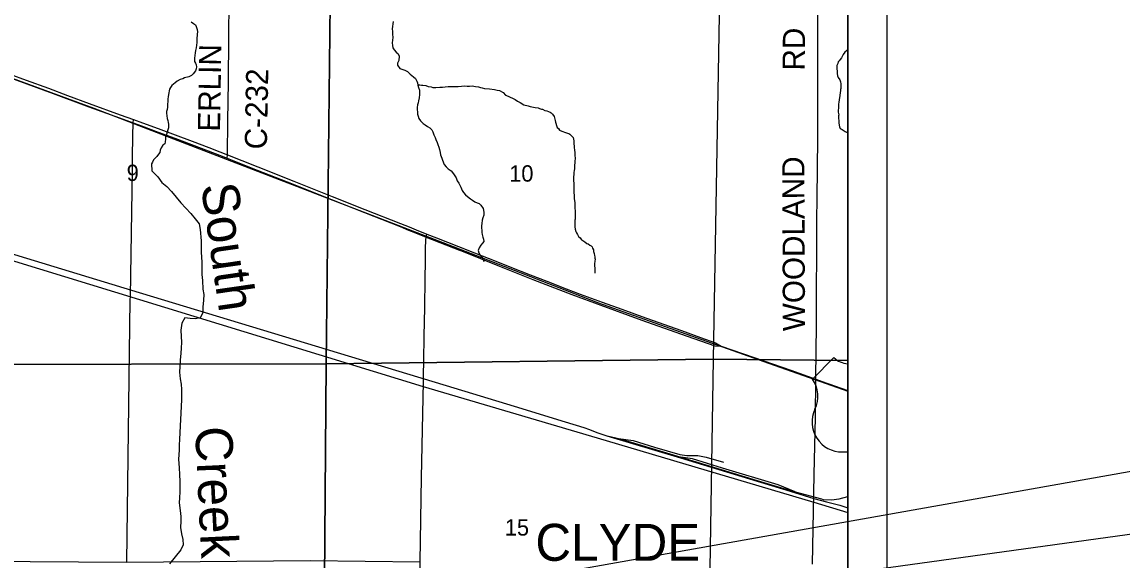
# Model space of a CAD drawing. Extents: x 36.7 to 70.7, y 0 to 22.
# Drawn here: x 43.478 to 46.296, y 17.404 to 18.785 of the extents above; entities that cross this region are included whole.
import ezdxf

# ---------------------------------------------------------------- set-up
doc = ezdxf.new("R2010")
doc.units = 0
for name, color, linetype in [('Default', 7, 'Continuous'), ('GM_X_Corporation_Text', 7, 'Continuous'), ('GM_X_County_Road', 7, 'Continuous'), ('GM_X_County_Road_Text', 7, 'Continuous'), ('GM_X_Minor_River', 7, 'Continuous'), ('GM_X_Minor_River_Text', 7, 'Continuous'), ('GM_X_Rail_Line', 7, 'Continuous'), ('GM_X_Section', 7, 'Continuous'), ('GM_X_Section_Text', 7, 'Continuous'), ('GM_X_State_Shield', 7, 'Continuous'), ('GM_X_Township_Road', 7, 'Continuous'), ('GM_X_Township_Road_Text', 7, 'Continuous'), ('GM_X_US_Route', 7, 'Continuous'), ('SH_Data', 7, 'Continuous'), ('SH_Text', 7, 'Continuous')]:
    doc.layers.add(name, color=color, linetype=linetype)

msp = doc.modelspace()

# ---------------------------------------------------------------- linework, layer by layer
at = {"layer": 'Default'}
for points in [[(45.5934, 17.918), (45.5934, 18.9006), (45.2652, 18.9013), (45.2484, 17.9213)], [(45.5934, 16.8994), (45.5934, 17.918), (45.2484, 17.9213), (45.2325, 16.9015)]]:
    msp.add_lwpolyline(points, close=True, dxfattribs=at)
at = {"layer": 'GM_X_County_Road'}
msp.add_line((45.503, 17.3961), (45.5047, 17.4867), dxfattribs=at)
for points in [[(44.0037, 18.4362), (44.004, 18.445), (44.0053, 18.5319), (44.0064, 18.6321), (44.0077, 18.7436), (44.0085, 18.8412), (44.0087, 18.9088), (44.0173, 19.4198)], [(45.5047, 17.4867), (45.5055, 17.532), (45.5076, 17.6263), (45.5108, 17.7725), (45.5115, 17.8705)], [(43.2502, 17.4045), (43.7467, 17.4014), (44.216, 17.4059), (44.498, 17.4024)]]:
    msp.add_lwpolyline(points, dxfattribs=at)
at = {"layer": 'GM_X_Minor_River'}
for points in [[(43.9114, 18.7853), (43.9174, 18.7815), (43.9219, 18.7773), (43.9241, 18.7731), (43.9267, 18.7654), (43.927, 18.7597), (43.9266, 18.7537), (43.926, 18.7408), (43.926, 18.7328), (43.9243, 18.7184), (43.9223, 18.712), (43.9215, 18.7059), (43.9194, 18.6926), (43.9194, 18.6885), (43.9201, 18.6835), (43.9223, 18.6793), (43.9242, 18.6751), (43.9249, 18.6698), (43.9244, 18.6653), (43.9221, 18.66), (43.9163, 18.6524), (43.9121, 18.6483), (43.9048, 18.6442), (43.8942, 18.6417), (43.8896, 18.6398), (43.8828, 18.638), (43.8755, 18.6331), (43.8701, 18.629), (43.8617, 18.6223), (43.8579, 18.6174), (43.8559, 18.6132), (43.8535, 18.5996), (43.8523, 18.5935), (43.8515, 18.5878), (43.851, 18.5833), (43.8509, 18.573), (43.8505, 18.567), (43.8493, 18.5609), (43.8481, 18.5556), (43.848, 18.5511), (43.8487, 18.5446), (43.8501, 18.5374)], [(44.4284, 18.7859), (44.428, 18.7802), (44.4271, 18.7737), (44.4263, 18.7677), (44.4266, 18.7605), (44.4269, 18.754), (44.4276, 18.7453), (44.4271, 18.7384), (44.4263, 18.732), (44.4266, 18.7252), (44.428, 18.7187), (44.431, 18.7133), (44.4366, 18.708), (44.4419, 18.7034), (44.4441, 18.6976), (44.4428, 18.6866), (44.4401, 18.6798), (44.4397, 18.6745), (44.446, 18.6657), (44.4509, 18.6642), (44.4589, 18.6618), (44.4653, 18.6579), (44.4724, 18.651), (44.481, 18.6449), (44.4859, 18.6402), (44.4893, 18.6338), (44.4911, 18.6288), (44.4918, 18.6235), (44.4932, 18.617), (44.4962, 18.6105), (44.4965, 18.6056), (44.4961, 18.5991), (44.4952, 18.5908), (44.494, 18.5832), (44.4924, 18.5783), (44.4912, 18.573), (44.4904, 18.5662), (44.4903, 18.5609), (44.491, 18.554)], [(45.5934, 18.7137), (45.5898, 18.7108), (45.5861, 18.7077), (45.5812, 18.702), (45.577, 18.6936), (45.5736, 18.6887), (45.5717, 18.6856), (45.5691, 18.6826), (45.5676, 18.6784), (45.565, 18.6738), (45.565, 18.6639), (45.5658, 18.6598), (45.5662, 18.6563), (45.5666, 18.6533), (45.567, 18.6469), (45.5685, 18.6427), (45.5727, 18.6366), (45.5747, 18.6321), (45.5758, 18.6268), (45.5759, 18.6211), (45.5755, 18.6146), (45.5748, 18.6119), (45.5744, 18.6089), (45.574, 18.604), (45.5729, 18.5964), (45.5715, 18.5853), (45.5704, 18.5796), (45.57, 18.5743), (45.57, 18.5717), (45.5697, 18.5679), (45.5697, 18.5648), (45.5686, 18.5584), (45.5686, 18.5542), (45.5698, 18.5508), (45.5702, 18.5474), (45.5698, 18.5447), (45.5698, 18.5367), (45.5702, 18.5337), (45.5703, 18.5268), (45.571, 18.5204), (45.5722, 18.5162), (45.5741, 18.512), (45.5791, 18.5094), (45.5867, 18.5049), (45.5934, 18.5007)], [(44.4921, 18.6223), (44.4944, 18.6239), (44.497, 18.6243), (44.5012, 18.6235), (44.505, 18.6232), (44.5122, 18.6221), (44.5187, 18.6202), (44.5259, 18.6187), (44.5301, 18.6176), (44.5377, 18.6176), (44.5483, 18.6181), (44.5555, 18.6181), (44.562, 18.6185), (44.5696, 18.6197), (44.5794, 18.6201), (44.5878, 18.6194), (44.595, 18.6202), (44.6041, 18.621), (44.6105, 18.6214), (44.6181, 18.6207), (44.6246, 18.6207), (44.6307, 18.6211), (44.6394, 18.62), (44.6474, 18.6185), (44.6523, 18.617), (44.6569, 18.6163), (44.663, 18.6148), (44.6751, 18.6137), (44.6884, 18.6123), (44.6949, 18.6108), (44.7009, 18.6093), (44.7108, 18.6044), (44.7169, 18.598), (44.7234, 18.5953), (44.7284, 18.5923), (44.7348, 18.5901), (44.7413, 18.5867), (44.747, 18.5825), (44.7542, 18.5792), (44.7638, 18.5727), (44.7744, 18.5705), (44.7801, 18.5686), (44.7923, 18.5657), (44.8002, 18.5649), (44.804, 18.5638), (44.8086, 18.5619), (44.8113, 18.5616), (44.817, 18.5586), (44.8227, 18.5571), (44.8269, 18.5556), (44.8307, 18.5541), (44.8337, 18.5526), (44.8368, 18.5488), (44.841, 18.5427), (44.8441, 18.5325), (44.8448, 18.5287), (44.8456, 18.526), (44.8472, 18.5203), (44.8491, 18.5147), (44.8521, 18.512), (44.8552, 18.5078), (44.8609, 18.5056), (44.8704, 18.5022), (44.8753, 18.5003), (44.8784, 18.4996), (44.8811, 18.4977), (44.8841, 18.4947), (44.8875, 18.4917), (44.8898, 18.489), (44.8918, 18.4807), (44.8918, 18.4738), (44.8926, 18.4662), (44.8926, 18.4628), (44.8934, 18.4575), (44.8938, 18.4499), (44.8942, 18.4442), (44.8947, 18.4351), (44.8943, 18.4287), (44.8939, 18.4245), (44.8932, 18.4184), (44.8929, 18.41), (44.8921, 18.4036), (44.8918, 18.4002), (44.8914, 18.3971), (44.8911, 18.3861), (44.8912, 18.3648), (44.8916, 18.3603), (44.8917, 18.347), (44.8921, 18.3417), (44.8925, 18.3333), (44.8933, 18.3272), (44.8937, 18.3227), (44.8937, 18.32), (44.8941, 18.3155), (44.8945, 18.3071), (44.8946, 18.3022), (44.895, 18.2965), (44.8946, 18.2931), (44.8946, 18.2836), (44.8947, 18.2801), (44.8943, 18.2775)], [(44.491, 18.554), (44.4913, 18.5487), (44.4928, 18.5438), (44.4942, 18.5377), (44.4991, 18.5319), (44.5055, 18.5247), (44.5104, 18.5212), (44.5164, 18.5177), (44.5228, 18.5138), (44.528, 18.5092), (44.5299, 18.5035), (44.5328, 18.4963), (44.5362, 18.489), (44.5384, 18.4841), (44.5417, 18.4764), (44.5428, 18.4715), (44.5457, 18.4646), (44.5472, 18.4585), (44.5494, 18.4505), (44.5501, 18.4448), (44.5534, 18.4365), (44.5548, 18.4307), (44.5596, 18.4197), (44.5645, 18.4139), (44.5698, 18.4093), (44.5777, 18.4039), (44.5829, 18.3959), (44.5866, 18.3906), (44.59, 18.3856), (44.5929, 18.378), (44.5967, 18.3726), (44.5992, 18.3669), (44.6022, 18.3619), (44.6052, 18.3532), (44.6085, 18.3482), (44.6141, 18.3421), (44.6194, 18.3378), (44.6269, 18.3317), (44.6322, 18.3286), (44.6382, 18.324), (44.6435, 18.322), (44.6488, 18.3204), (44.6537, 18.3158), (44.6596, 18.307), (44.661, 18.2983), (44.6606, 18.2899), (44.6586, 18.2835), (44.657, 18.2771), (44.6562, 18.2691), (44.6553, 18.2627), (44.6553, 18.2573), (44.6556, 18.252), (44.6559, 18.2456), (44.6566, 18.2406), (44.6588, 18.2342), (44.6602, 18.2285), (44.6609, 18.2231), (44.6578, 18.2182), (44.6532, 18.2133), (44.649, 18.2066), (44.6466, 18.1994), (44.6481, 18.1937), (44.6514, 18.1876), (44.6563, 18.1818), (44.6593, 18.1768), (44.6607, 18.1719)], [(43.8501, 18.5374), (43.8512, 18.5328), (43.8523, 18.5275), (43.853, 18.5229), (43.8529, 18.5138), (43.8517, 18.5089), (43.8497, 18.5025), (43.8478, 18.4972), (43.845, 18.4911), (43.8457, 18.4847), (43.8449, 18.4782), (43.8441, 18.4733), (43.8383, 18.4692), (43.8341, 18.4628), (43.8317, 18.4563), (43.8305, 18.451), (43.8278, 18.4461), (43.8232, 18.4409), (43.8194, 18.4367), (43.8144, 18.4319), (43.812, 18.4258), (43.8098, 18.4215)], [(43.8098, 18.4215), (43.8103, 18.4034), (43.8256, 18.3881), (43.8361, 18.3736), (43.8485, 18.3639), (43.8605, 18.3505), (43.8728, 18.3363), (43.8844, 18.3222), (43.8976, 18.3084), (43.9103, 18.2949), (43.9215, 18.2808), (43.932, 18.2681), (43.9341, 18.2537), (43.9368, 18.2248), (43.9367, 18.2112), (43.9372, 18.1956), (43.9378, 18.1827), (43.9381, 18.1698), (43.9383, 18.1557), (43.9385, 18.1386), (43.9398, 18.1231), (43.9411, 18.1007), (43.9436, 18.087), (43.9427, 18.0726), (43.9413, 18.0547), (43.9408, 18.0403), (43.9342, 18.0271), (43.9212, 18.025), (43.9083, 18.0255), (43.8947, 18.0275), (43.8873, 18.0132), (43.8845, 17.9954), (43.8858, 17.9798), (43.8868, 17.9646), (43.8855, 17.9494), (43.8846, 17.9365), (43.8828, 17.9191), (43.8823, 17.9024), (43.8814, 17.8884), (43.8827, 17.8713), (43.8856, 17.8576), (43.8865, 17.8439), (43.8868, 17.8314), (43.8862, 17.8174), (43.8817, 17.7168), (43.8807, 17.7009), (43.8802, 17.688), (43.8784, 17.6649), (43.8808, 17.6428), (43.8814, 17.6257), (43.8823, 17.6083), (43.8825, 17.5954), (43.8824, 17.5813), (43.8811, 17.5661), (43.8805, 17.5532), (43.8833, 17.5339), (43.8851, 17.5187), (43.8849, 17.5061), (43.8836, 17.4902), (43.8868, 17.4742), (43.8897, 17.4598), (43.8907, 17.4457), (43.8845, 17.4333), (43.8557, 17.3975)], [(44.8943, 18.2775), (44.894, 18.2687), (44.894, 18.263), (44.8944, 18.2604), (44.8952, 18.2543), (44.8963, 18.2486), (44.8983, 18.2452), (44.9013, 18.2407), (44.9036, 18.2357), (44.9078, 18.232), (44.9109, 18.2274), (44.9147, 18.2255), (44.9196, 18.2222), (44.9246, 18.218), (44.928, 18.2169), (44.9326, 18.2135), (44.9356, 18.212), (44.9387, 18.2089), (44.9394, 18.2059), (44.9417, 18.2014), (44.9421, 18.1972), (44.9433, 18.1919), (44.9441, 18.1869), (44.9452, 18.1839), (44.9456, 18.1805), (44.946, 18.1778), (44.9457, 18.1721), (44.9446, 18.1657), (44.9442, 18.1623), (44.9442, 18.1596), (44.945, 18.1554), (44.9454, 18.1528), (44.9454, 18.1493), (44.9451, 18.1455), (44.9455, 18.1418)]]:
    msp.add_lwpolyline(points, dxfattribs=at)
at = {"layer": 'GM_X_Rail_Line'}
msp.add_line((44.9808, 17.724), (45.0063, 17.7185), dxfattribs=at)
for points in [[(39.9505, 19.9142), (40.2796, 19.7934), (40.742, 19.6245), (41.298, 19.4193), (41.8828, 19.2032), (42.4402, 19.0032), (43.0913, 18.7734), (43.6618, 18.5644), (44.5563, 18.22), (44.9526, 18.0665), (45.405, 17.9057), (45.5934, 17.8393)], [(39.4351, 19.5275), (39.5072, 19.4857), (39.6526, 19.4084), (39.8435, 19.3143), (39.9823, 19.2538), (40.1053, 19.2054), (40.2394, 19.1588), (40.707, 19.0117), (41.5752, 18.749), (42.4154, 18.492), (43.2547, 18.2349), (44.5058, 17.8517), (44.9515, 17.7199), (45.506, 17.5551), (45.5934, 17.5283)], [(43.259, 18.2503), (43.7587, 18.0984), (44.3412, 17.9214), (44.5645, 17.8537), (44.7384, 17.8009), (44.8692, 17.7613), (44.9175, 17.7461), (44.9313, 17.7411), (44.9509, 17.7339), (44.9637, 17.7294), (44.9762, 17.7254), (45.1649, 17.6685), (45.3609, 17.6087), (45.4457, 17.5831), (45.5064, 17.5649), (45.539, 17.5556), (45.5559, 17.5513), (45.5732, 17.5471), (45.5934, 17.541)], [(45.0063, 17.7185), (45.0099, 17.7177), (45.1655, 17.6707)], [(45.0063, 17.7185), (45.0436, 17.7129), (45.0979, 17.696), (45.1631, 17.6771), (45.1813, 17.6749), (45.2095, 17.675), (45.2302, 17.67), (45.275, 17.6577)], [(45.4586, 17.582), (45.4148, 17.5993), (45.2721, 17.6423), (45.1958, 17.6662), (45.1655, 17.6707)], [(45.1655, 17.6707), (45.3616, 17.611), (45.4463, 17.5853), (45.4586, 17.582)], [(45.4586, 17.582), (45.526, 17.5634), (45.53, 17.5623), (45.5519, 17.5607), (45.5717, 17.564), (45.5934, 17.5694)]]:
    msp.add_lwpolyline(points, dxfattribs=at)
at = {"layer": 'GM_X_Section'}
for points in [[(44.2682, 18.9088), (44.2567, 17.9094), (43.2576, 17.9081), (43.2658, 18.9165)], [(45.2652, 18.9013), (45.2484, 17.9213), (44.2567, 17.9094), (44.2682, 18.9088)], [(44.2567, 17.9094), (44.2493, 16.9097), (43.2397, 16.908), (43.2576, 17.9081)], [(45.2484, 17.9213), (45.2325, 16.9015), (44.2493, 16.9097), (44.2567, 17.9094)]]:
    msp.add_lwpolyline(points, close=True, dxfattribs=at)
at = {"layer": 'GM_X_State_Shield'}
for p, q in [((45.5577, 17.9254), (45.5028, 17.8704)), ((45.5934, 17.6836), (45.5934, 17.9097)), ((45.5797, 17.6837), (45.5907, 17.6837))]:
    msp.add_line(p, q, dxfattribs=at)
for centre, radius, start, end in [((45.5962, 17.9646), 0.0549, 225.573, 267.114), ((45.4398, 17.8263), 0.0769, 334.5471, 35.0009), ((45.5788, 17.7606), 0.0769, 154.8319, 270.6383), ((45.5907, 17.6287), 0.0549, 87.1541, 90)]:
    msp.add_arc(centre, radius, start, end, dxfattribs=at)
at = {"layer": 'GM_X_Township_Road'}
msp.add_line((44.5066, 17.8735), (44.5092, 18.0235), dxfattribs=at)
for points in [[(45.5934, 14.0969), (45.5934, 19.8832), (45.2981, 19.8785), (45.2722, 19.8781), (44.0656, 19.8618), (44.0245, 19.8612), (43.3189, 19.8494)], [(45.5149, 18.3335), (45.5165, 18.4864), (45.5165, 18.7604), (45.5166, 18.9055)], [(43.7613, 18.4377), (43.762, 18.4934), (43.7627, 18.5265), (43.7633, 18.535)], [(43.7554, 18.082), (43.7609, 18.4069), (43.7613, 18.4377)], [(45.5131, 18.0081), (45.5131, 18.0111), (45.5143, 18.2773), (45.5149, 18.3335)], [(44.5108, 18.1338), (44.5113, 18.1659), (44.5119, 18.205), (44.5127, 18.2264), (44.5134, 18.2337), (44.5149, 18.2418)], [(44.5092, 18.0235), (44.5096, 18.0465), (44.5108, 18.1338)], [(43.7467, 17.4014), (43.7552, 18.0731), (43.7554, 18.082)], [(45.5115, 17.8705), (45.5116, 17.8737), (45.5131, 18.0081)], [(44.4801, 16.4056), (44.498, 17.4024), (44.5009, 17.6179), (44.5064, 17.8635), (44.5066, 17.8735)]]:
    msp.add_lwpolyline(points, dxfattribs=at)
at = {"layer": 'GM_X_US_Route'}
for points in [[(43.262, 18.7192), (43.3034, 18.7041), (43.3522, 18.6861), (43.4462, 18.6516), (43.4883, 18.6361), (43.5456, 18.6151), (43.5947, 18.597), (43.6501, 18.5766), (43.7293, 18.5476), (43.7633, 18.535), (43.7861, 18.5267), (43.8268, 18.5118), (43.8699, 18.4959), (43.9134, 18.4799), (43.9561, 18.4638), (43.9846, 18.4527), (44.004, 18.445), (44.0406, 18.4305), (44.0821, 18.4139), (44.1738, 18.3777), (44.2724, 18.3384), (44.3565, 18.3051), (44.4477, 18.2689), (44.4696, 18.2601)], [(43.2619, 18.7104), (43.3516, 18.6776), (43.4647, 18.6361), (43.5573, 18.6019), (43.6494, 18.5681), (43.7274, 18.5394), (43.7627, 18.5265), (43.784, 18.5188), (43.8265, 18.503), (43.8696, 18.4872), (43.9118, 18.4714), (43.9545, 18.4552), (43.9835, 18.444), (44.0037, 18.4362), (44.0806, 18.4058), (44.1723, 18.3695), (44.2709, 18.3302), (44.355, 18.297), (44.4462, 18.2608), (44.4681, 18.2519)], [(44.4681, 18.2519), (44.4863, 18.2446), (44.5134, 18.2337), (44.5983, 18.2006), (44.6076, 18.1968)], [(44.4696, 18.2601), (44.4878, 18.2527), (44.5149, 18.2418)], [(44.5149, 18.2418), (44.5398, 18.2322), (44.596, 18.2099), (44.6371, 18.1937), (44.6919, 18.1722), (44.7273, 18.1583), (44.7797, 18.1378), (44.8222, 18.1209), (44.872, 18.1014), (44.9075, 18.0881), (44.9645, 18.0673), (45.0146, 18.0494), (45.0661, 18.0309), (45.1071, 18.0163), (45.1673, 17.9946), (45.2159, 17.9771), (45.2549, 17.9631), (45.2693, 17.9544)], [(44.6076, 18.1968), (44.6971, 18.1612), (44.7869, 18.1256), (44.886, 18.0869), (44.9603, 18.0595), (45.0654, 18.0216), (45.1651, 17.9865), (45.216, 17.9684), (45.2528, 17.9559), (45.2693, 17.9544)], [(45.2693, 17.9544), (45.3533, 17.9255), (45.4478, 17.8928), (45.5115, 17.8705), (45.5399, 17.8602)], [(45.5399, 17.8602), (45.5446, 17.8585), (45.5934, 17.8414)]]:
    msp.add_lwpolyline(points, dxfattribs=at)
at = {"layer": 'SH_Data'}
for p, q in [((45.6934, 20.9969), (45.6934, 13.9969)), ((45.5934, 20.8969), (45.5934, 14.0969))]:
    msp.add_line(p, q, dxfattribs=at)
at = {"layer": 'SH_Text'}
msp.add_lwpolyline([(47.1799, 17.7861), (42.2435, 16.9102), (47.1799, 17.5925)], close=True, dxfattribs=at)

# ---------------------------------------------------------------- texts
at = {"layer": 'GM_X_Corporation_Text'}
msp.add_text('CLYDE', height=0.0947, rotation=0, dxfattribs=at).set_placement((44.7931, 17.4049))
at = {"layer": 'GM_X_County_Road_Text'}
for s, rotation, p in [('ERLIN', 89.0651, (43.985, 18.5039)), ('C-232', 88.8978, (44.105, 18.4583))]:
    msp.add_text(s, height=0.05682, rotation=rotation, dxfattribs=at).set_placement(p)
at = {"layer": 'GM_X_Minor_River_Text'}
for s, rotation, p in [('South', 278.2239, (43.936, 18.3666)), ('Creek', 272.7558, (43.921, 17.7473))]:
    msp.add_text(s, height=0.09474, rotation=rotation, dxfattribs=at).set_placement(p)
at = {"layer": 'GM_X_Section_Text'}
for s, height, p in [('9', 0.0419, (43.7459, 18.3777)), ('10', 0.04186, (44.7259, 18.3761)), ('15', 0.04186, (44.7146, 17.4695))]:
    msp.add_text(s, height=height, rotation=0, dxfattribs=at).set_placement(p)
at = {"layer": 'GM_X_Township_Road_Text'}
for s, rotation, p in [('RD', 89.5045, (45.4831, 18.6604)), ('WOODLAND', 90.2333, (45.4839, 17.9933))]:
    msp.add_text(s, height=0.05682, rotation=rotation, dxfattribs=at).set_placement(p)

doc.saveas('drawing.dxf')
